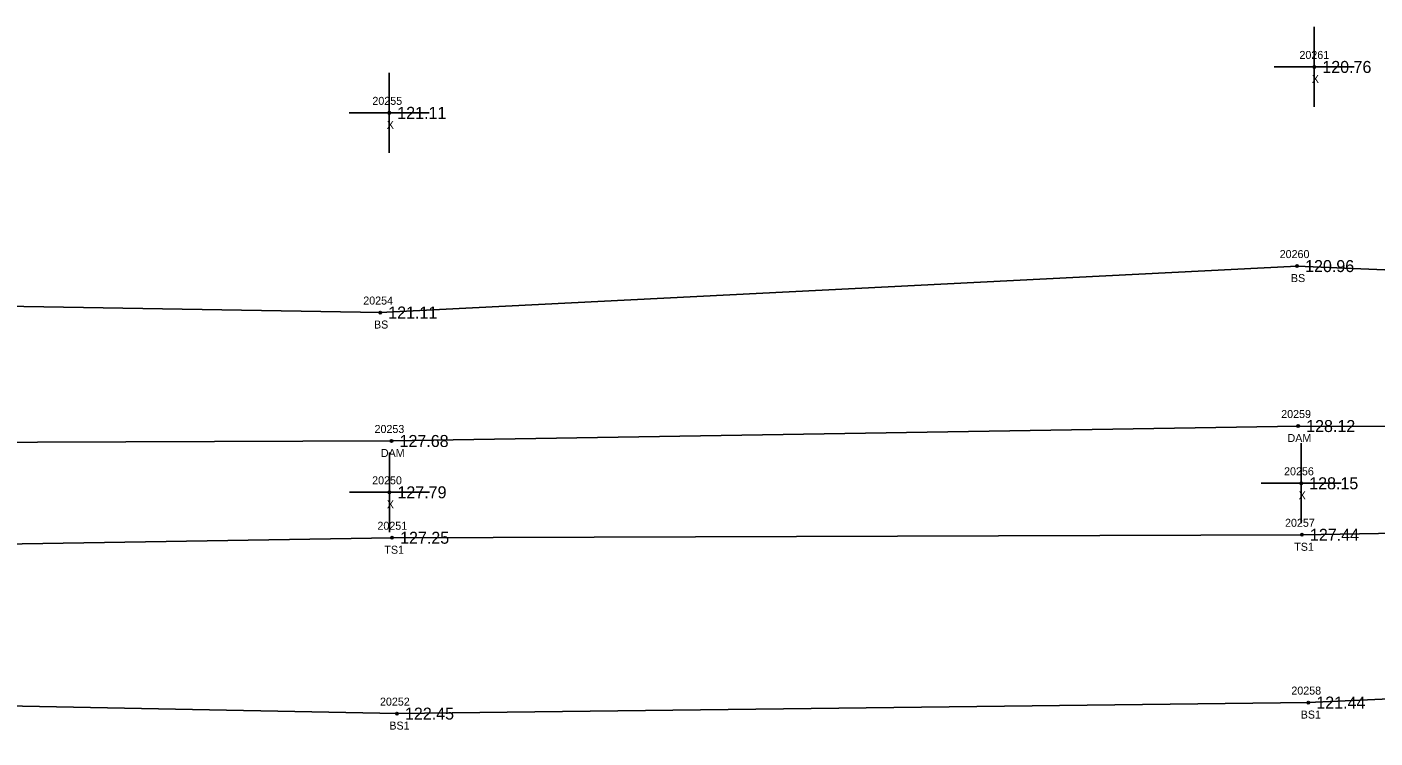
# Model space of a CAD drawing. Extents: x 2375812 to 2377225, y 1024470 to 1025135.
# Drawn here: x 2376046.3 to 2376214.8, y 1025037.3 to 1025126.2 of the extents above; entities that cross this region are included whole.
import ezdxf

# ---------------------------------------------------------------- set-up
doc = ezdxf.new("R2010")
doc.units = 0
for name, color, linetype in [('RD_DTM_BkLn2', 7, 'Continuous'), ('RD_DTM_BkLn_txCode', 7, 'Continuous'), ('RD_EX_Dam', 7, 'Continuous'), ('RD_EX_Dam_txCode', 7, 'Continuous'), ('RD_EX_Misc', 7, 'Continuous'), ('RD_EX_Misc_txCode', 7, 'Continuous'), ('RD_EX_TX_Dam_ELEV', 7, 'Continuous'), ('RD_EX_TX_Misc_ELEV', 7, 'Continuous'), ('RD_SMD_Locator', 7, 'Continuous')]:
    doc.layers.add(name, color=color, linetype=linetype)

msp = doc.modelspace()

# ---------------------------------------------------------------- linework, layer by layer
at = {"layer": 'RD_DTM_BkLn2'}
for points in [[(2375847.51, 1025092.15), (2375876.46, 1025088.72), (2375981.63, 1025092.39), (2376090.5, 1025090.54), (2376205.11, 1025096.35), (2376313.64, 1025091.79), (2376415.11, 1025100.3), (2376448.24, 1025100.64), (2376465.02, 1025111.39), (2376486.46, 1025115.19), (2376497.97, 1025114.18)], [(2375847.93, 1025050.33), (2375875.91, 1025056.72), (2375981.44, 1025060.56), (2376091.98, 1025062.38), (2376205.71, 1025062.75), (2376313.72, 1025064.62), (2376418.13, 1025064.73), (2376493.03, 1025062.01)], [(2375848.17, 1025037.34), (2375876.1, 1025042.73), (2375981.89, 1025042.57), (2376092.59, 1025040.39), (2376206.51, 1025041.77), (2376314.64, 1025046.65), (2376420.66, 1025046.91), (2376483.6, 1025044.87), (2376501.85, 1025058.56), (2376497.33, 1025064.77)]]:
    msp.add_lwpolyline(points, dxfattribs=at)
at = {"layer": 'RD_EX_Dam'}
msp.add_lwpolyline([(2375847.73, 1025068.2), (2375876.5, 1025071.72), (2375981.19, 1025074.08), (2376091.91, 1025074.48), (2376205.24, 1025076.35), (2376314.21, 1025075.97), (2376418.29, 1025077.81), (2376454.32, 1025078.43), (2376493.3, 1025082.7)], dxfattribs=at)
at = {"layer": 'RD_EX_Misc'}
for p, q in [((2376207.26, 1025116.25), (2376207.26, 1025126.25)), ((2376202.26, 1025121.25), (2376212.26, 1025121.25)), ((2376091.63, 1025110.51), (2376091.63, 1025120.51)), ((2376086.63, 1025115.51), (2376096.63, 1025115.51)), ((2376205.62, 1025064.19), (2376205.62, 1025074.19)), ((2376091.65, 1025063.06), (2376091.65, 1025073.06)), ((2376200.62, 1025069.19), (2376210.62, 1025069.19)), ((2376086.65, 1025068.06), (2376096.65, 1025068.06))]:
    msp.add_line(p, q, dxfattribs=at)
at = {"layer": 'RD_SMD_Locator'}
for centre in [(2376207.26, 1025121.25), (2376091.63, 1025115.51), (2376205.11, 1025096.35), (2376090.5, 1025090.54), (2376205.24, 1025076.35), (2376091.91, 1025074.48), (2376205.62, 1025069.19), (2376091.65, 1025068.06), (2376091.98, 1025062.38), (2376205.71, 1025062.75), (2376206.51, 1025041.77), (2376092.59, 1025040.39)]:
    msp.add_circle(centre, 0.15, dxfattribs=at)

# ---------------------------------------------------------------- texts
at = {"layer": 'RD_DTM_BkLn_txCode'}
for s, p in [('20260', (2376202.93, 1025097.35)), ('BS', (2376204.33, 1025094.35)), ('20254', (2376088.38, 1025091.54)), ('BS', (2376089.72, 1025088.54)), ('20251', (2376090.15, 1025063.38)), ('20257', (2376203.6, 1025063.75)), ('TS1', (2376204.75, 1025060.75)), ('TS1', (2376091.02, 1025060.38)), ('20258', (2376204.39, 1025042.77)), ('20252', (2376090.47, 1025041.39)), ('BS1', (2376205.56, 1025039.77)), ('BS1', (2376091.64, 1025038.39))]:
    msp.add_text(s, height=1, dxfattribs=at).set_placement(p)
at = {"layer": 'RD_EX_Dam_txCode'}
for s, p in [('20259', (2376203.12, 1025077.35)), ('20253', (2376089.79, 1025075.48)), ('DAM', (2376203.91, 1025074.35)), ('DAM', (2376090.58, 1025072.48))]:
    msp.add_text(s, height=1, dxfattribs=at).set_placement(p)
at = {"layer": 'RD_EX_Misc_txCode'}
for s, p in [('20261', (2376205.4, 1025122.25)), ('X', (2376206.95, 1025119.25)), ('20255', (2376089.52, 1025116.51)), ('X', (2376091.32, 1025113.51)), ('20256', (2376203.48, 1025070.19)), ('20250', (2376089.49, 1025069.06)), ('X', (2376091.33, 1025066.06)), ('X', (2376205.3, 1025067.19))]:
    msp.add_text(s, height=1, dxfattribs=at).set_placement(p)
at = {"layer": 'RD_EX_TX_Dam_ELEV'}
for s, p in [('128.12', (2376206.24, 1025075.6)), ('127.68', (2376092.91, 1025073.73))]:
    msp.add_text(s, height=1.5, dxfattribs=at).set_placement(p)
at = {"layer": 'RD_EX_TX_Misc_ELEV'}
for s, p in [('120.76', (2376208.26, 1025120.5)), ('121.11', (2376092.63, 1025114.76)), ('120.96', (2376206.11, 1025095.6)), ('121.11', (2376091.5, 1025089.79)), ('127.79', (2376092.65, 1025067.31)), ('128.15', (2376206.62, 1025068.44)), ('127.44', (2376206.71, 1025062)), ('127.25', (2376092.98, 1025061.63)), ('121.44', (2376207.51, 1025041.02)), ('122.45', (2376093.59, 1025039.64))]:
    msp.add_text(s, height=1.5, dxfattribs=at).set_placement(p)

doc.saveas('drawing.dxf')
